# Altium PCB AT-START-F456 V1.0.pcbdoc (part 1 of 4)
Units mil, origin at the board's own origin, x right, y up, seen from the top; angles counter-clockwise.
Board outline 10942.5 x 3554 mil, 2 copper layers (Top Layer, Bottom Layer); 156 components, 201 nets, 759 pads, 796 vias.
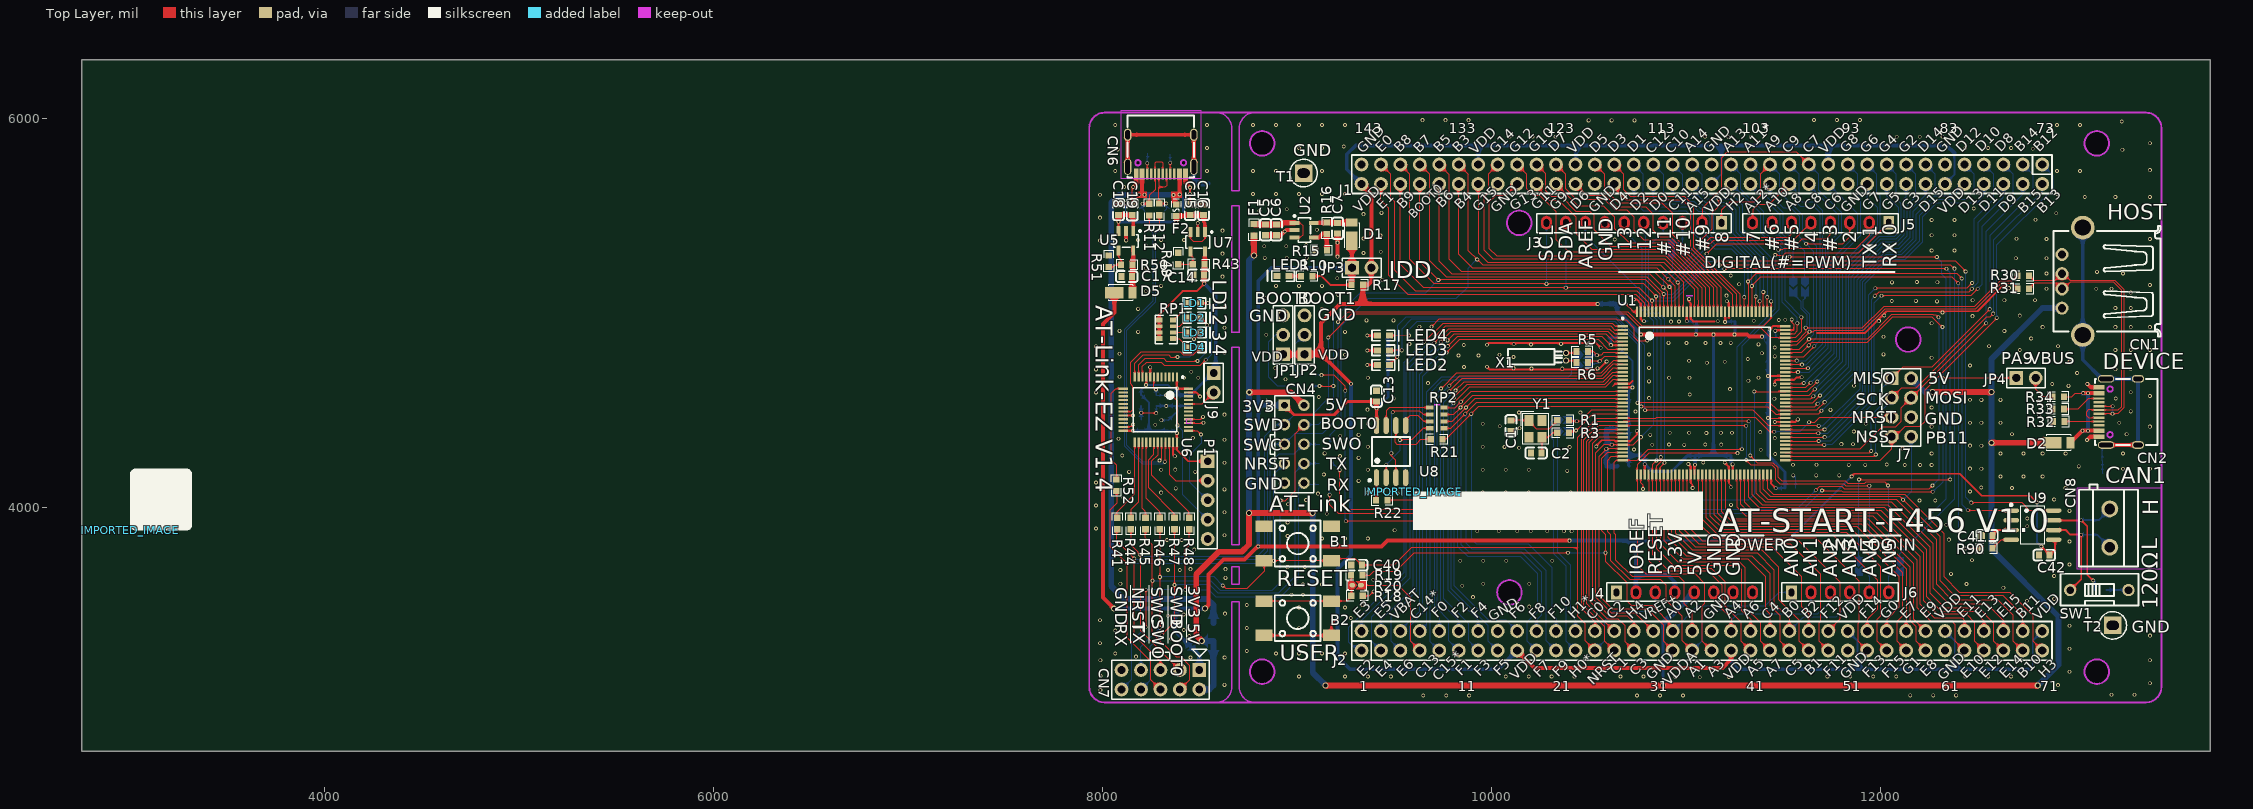
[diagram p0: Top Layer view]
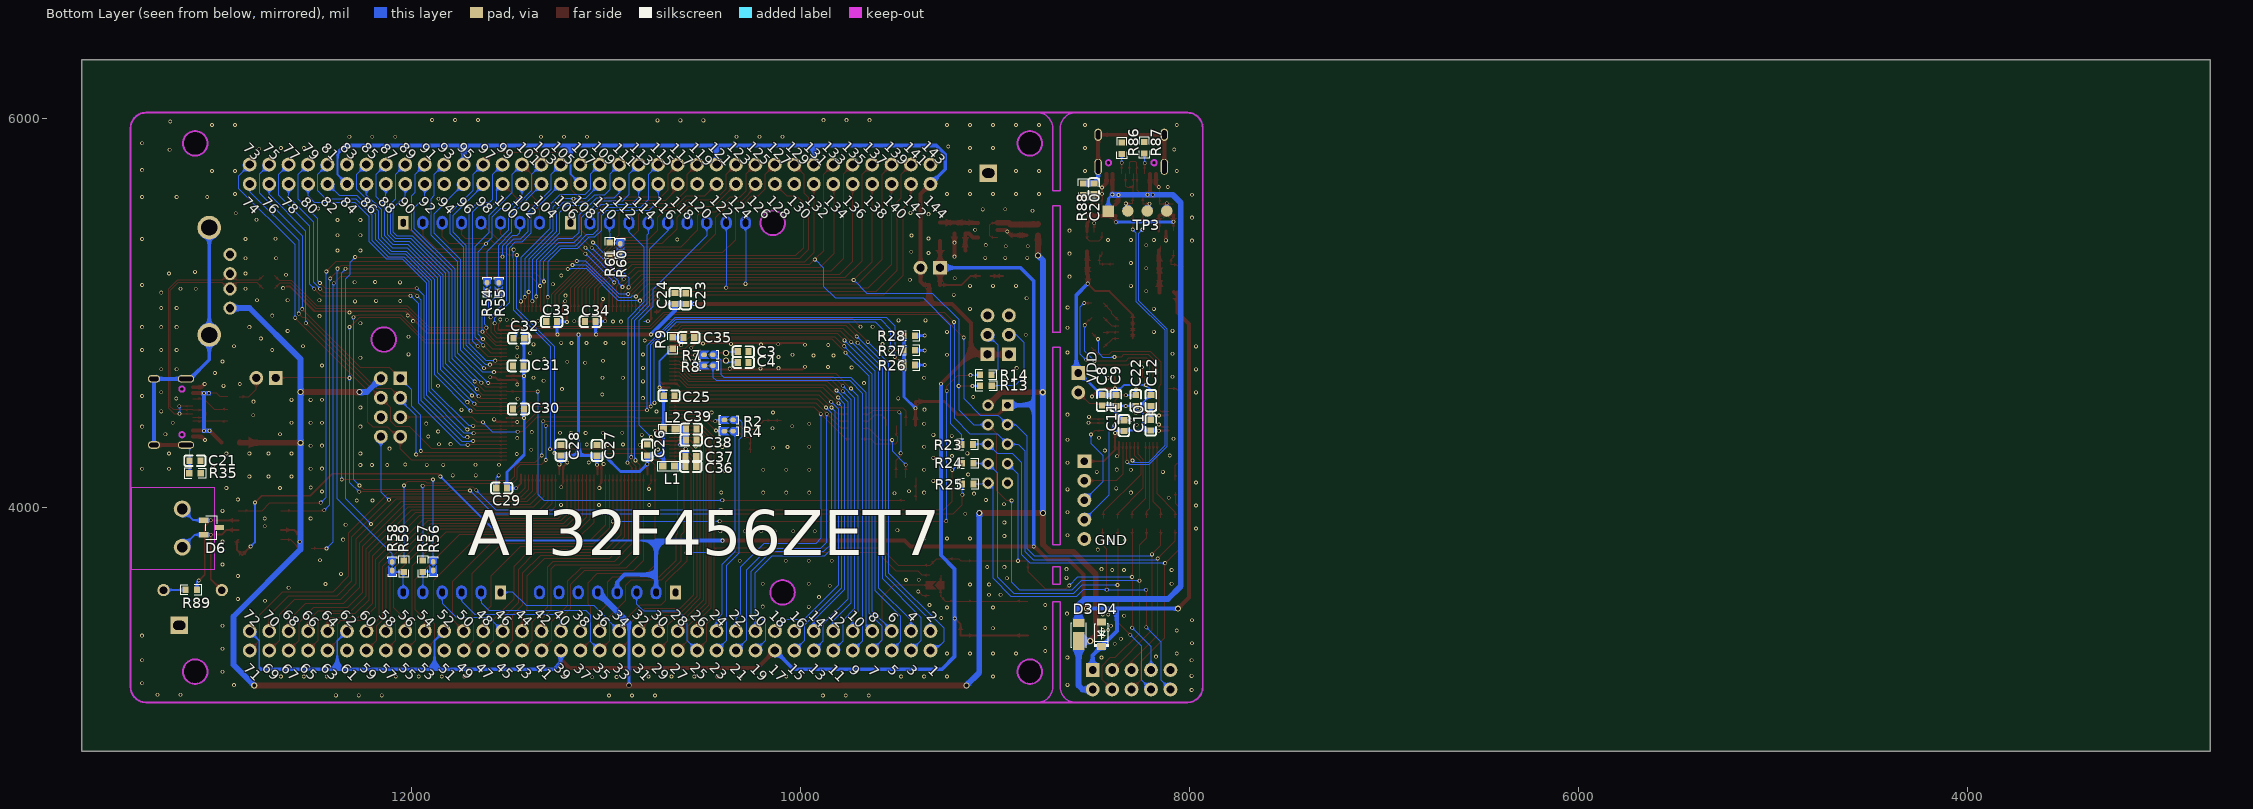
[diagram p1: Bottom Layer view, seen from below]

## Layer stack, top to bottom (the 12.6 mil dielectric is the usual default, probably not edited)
Top Layer: signal copper (thickness not stored)
Dielectric: dielectric 12.6, FR-4, Dk 4.8
Bottom Layer: signal copper (thickness not stored)

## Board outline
13692.5,2750 2750,2750 2750,6304 13692.5,6304
cut-out: 12202.8,4865.97 ccw(c12139.81,4865.43) 12076.82,4865.97 ccw(c12139.81,4866.51)
cut-out: 10202.8,5465.96 ccw(c10139.81,5465.42) 10076.82,5465.96 ccw(c10139.81,5466.5)
cut-out: 10152.8,3565.97 ccw(c10089.81,3565.43) 10026.82,3565.97 ccw(c10089.81,3566.51)
cut-out: 8881.38,5874.63 ccw(c8818.39,5874.09) 8755.4,5874.63 ccw(c8818.39,5875.17)
cut-out: 8881.38,3158.09 ccw(c8818.39,3157.55) 8755.4,3158.09 ccw(c8818.39,3158.63)
cut-out: 13172.72,3158.09 ccw(c13109.73,3157.55) 13046.74,3158.09 ccw(c13109.73,3158.63)
cut-out: 13172.72,5874.63 ccw(c13109.73,5874.09) 13046.74,5874.63 ccw(c13109.73,5875.17)

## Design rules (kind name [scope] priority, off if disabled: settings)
BoardOutlineClearance copperThickness1oz [All] p0: genericclearance=10 ignorepadtopadclearanceinfootprint=FALSE except(0: Arc-SplitContinuation Track-SplitContinuation SMDPad-SplitContinuation THPad-SplitContinuation Via-SplitContinuation Fill-SplitContinuation Poly-SplitContinuation Region-SplitContinuation Text-SplitContinuation; 6: SMDPad-CutoutEdge THPad-CutoutEdge Via-CutoutEdge Fill-CutoutEdge Region-CutoutEdge; 11.8: Track-OutlineEdge SMDPad-OutlineEdge THPad-OutlineEdge Via-OutlineEdge Fill-OutlineEdge Region-OutlineEdge Poly-OutlineEdge Text-OutlineEdge Track-CutoutEdge)
Clearance copperThickness1oz [(InNet('GND') OR InNet('PB11') OR InNet('PD4') OR InNet('PA1') OR InNet('PC1') OR InNet('PE15') OR InNet('PB10') OR InNet('PG6') OR InNet('PD10') OR InNet('PD9') OR InNet('PD8') OR InNet('PG15') OR InNet('PA2') OR InNet('PC0') OR InNet('PC2') OR InNet('NRST') OR InNet('PA15') OR InNet('PA13/SWDIO') OR InNet('PA14/SWCLK') OR InNet('VDD') OR InNet('PA3') OR InNet('PB2/BOOT1') OR InNet('3V3') OR InNet('PA0') OR InNet('PA5') OR InNet('PA6') OR InNet('PA7') OR InNet('PA9') OR InNet('PA10') OR InNet('PG14') OR InNet('PG13') OR InNet('PG11') OR InNet('PB5') OR InNet('PB6') OR InNet('PD2') OR InNet('PC12') OR InNet('PC11') OR InNet('PC10') OR InNet('VBAT') OR InNet('VDDA') OR InNet('VREF+') OR InNet('PD11') OR InNet('PD12') OR InNet('PD13') OR InNet('PD14') OR InNet('PD15') OR InNet('PG2') OR InNet('PG3') OR InNet('PG4') OR InNet('PG5') OR InNet('PG7') OR InNet('PG8') OR InNet('PC6') OR InNet('PC7') OR InNet('PC8') OR InNet('PC9') OR InNet('PA8') OR InNet('PH2') OR InNet('PH0/HEXT_IN') OR InNet('PH1/HEXT_OUT') OR InNet('PF10') OR InNet('PF9') OR InNet('PF8') OR InNet('PF7') OR InNet('PF6') OR InNet('PF5') OR InNet('PF4') OR InNet('PF3') OR InNet('PF2') OR InNet('PF1') OR InNet('PF0') OR InNet('PC13') OR InNet('PE6') OR InNet('PE5') OR InNet('PE4') OR InNet('PE3') OR InNet('PE2') OR InNet('PC15/LEXT_OUT') OR InNet('PC14/LEXT_IN') OR InNet('SWO') OR InNet('ATLK_RX') OR InNet('LD4') OR InNet('VCC') OR InNet('M-NRST') OR InNet('ATLK_TX') OR InNet('ATLINK_5V') OR InNet('PH3') OR InNet('PB3') OR InNet('QSPI1_IO2') OR InNet('QSPI1_IO1') OR InNet('PB4') OR InNet('PH1_E') OR InNet('PH0_E') OR InNet('PC15_E') OR InNet('PC14_E') OR InNet('PA11_E') OR InNet('PA12_E') OR InNet('PB0') OR InNet('PA4') OR InNet('PE10') OR InNet('PC4') OR InNet('VCC3.5V') OR InNet('PG0') OR InNet('PE7') OR InNet('PE8') OR InNet('PG1') OR InNet('LD3') OR InNet('LD2') OR InNet('LD1') OR InNet('VBUS1') OR InNet('PD3') OR InNet('PG9') OR InNet('PD6') OR InNet('M-SWDIO') OR InNet('M-ATLK_RX') OR InNet('M-ATLK_TX') OR InNet('PE1') OR InNet('PC3') OR InNet('PD7') OR InNet('PG10') OR InNet('PG12') OR InNet('M-SWCLK') OR InNet('PC5') OR InNet('PE12') OR InNet('PE11') OR InNet('PF15') OR InNet('PF14') OR InNet('PE13') OR InNet('PE14') OR InNet('PE9') OR InNet('PF12') OR InNet('PF13') OR InNet('PB1') OR InNet('PD5') OR InNet('PE0') OR InNet('QSPI1_SCK') OR InNet('PF11') OR InNet('QSPI1_IO0') OR InNet('QSPI1_IO3') OR InNet('$2N452') OR InNet('$2N453') OR InNet('$2N511') OR InNet('$2N512') OR InNet('$2N702') OR InNet('$2N701') OR InNet('$3N82') OR InNet('$3N81') OR InNet('$3N119') OR InNet('$3N184') OR InNet('$3N504') OR InNet('$3N505') OR InNet('$3N506') OR InNet('$4N269') OR InNet('$4N270') OR InNet('$4N339') OR InNet('$3N58') OR InNet('EGND1') OR InNet('OTGFS1_D-') OR InNet('OTGFS1_D+') OR InNet('PB12') OR InNet('PB13') OR InNet('PB14') OR InNet('PB15') OR InNet('PH4') OR InNet('QSPI1_CS') OR InNet('$3N17593') OR InNet('ATLK_SWCLK') OR InNet('$6N17598') OR InNet('ATLK_SWDIO') OR InNet('ATLK_BOOT0') OR InNet('ATLK_NRST') OR InNet('$6N17675') OR InNet('ATLK_SWO') OR InNet('PA11') OR InNet('PA12') OR InNet('$6N16959') OR InNet('EGND') OR InNet('$3N17443') OR InNet('$3N17484') OR InNet('CC2') OR InNet('USBP') OR InNet('USBM') OR InNet('CC1') OR InNet('M-BOOT0') OR InNet('$6N792') OR InNet('$6N793') OR InNet('$6N794') OR InNet('$6N795') OR InNet('M-USB_DP') OR InNet('M-USB_DM') OR InNet('5V') OR InNet('BOOT0') OR InNet('CAN_H') OR InNet('CAN_L') OR InNet('$3N25805') OR InNet('$3N25576') OR InNet('CAN1_STB') OR InNet('CAN1_RX') OR InNet('CAN1_TX') OR InNet('PB8') OR InNet('PB9') OR InNet('VBUS'))] p1: gap=7 ignorepadtopadclearanceinfootprint=FALSE except(6: Track-Track Track-SMDPad SMDPad-SMDPad Track-THPad SMDPad-THPad THPad-THPad Track-Via SMDPad-Via THPad-Via Via-Via Track-Fill SMDPad-Fill THPad-Fill Via-Fill Fill-Fill SMDPad-Region THPad-Region Via-Region Fill-Region Region-Region Track-Poly SMDPad-Poly THPad-Poly Via-Poly Fill-Poly Poly-Poly Track-Text SMDPad-Text THPad-Text Via-Text Fill-Text Region-Text Poly-Text Text-Text; 6.9: Track-Hole SMDPad-Hole THPad-Hole Via-Hole Fill-Hole Region-Hole Poly-Hole Text-Hole Sheet-Hole; 11.8: Track-Region Region-Poly Track-Sheet SMDPad-Sheet THPad-Sheet Via-Sheet Fill-Sheet Region-Sheet Poly-Sheet Text-Sheet)
DiffPairsRouting differentialPair [All] p1: maxuncoupledlength=10 minlimit=5.9843 maxlimit=5.9843 mostfreqgap=5.9843 toplayer_minwidth=5 toplayer_prefwidth=10 toplayer_maxwidth=100 bottomlayer_minwidth=5 bottomlayer_prefwidth=10 bottomlayer_maxwidth=100
PasteMaskExpansion pasteMaskExpansion [All] p1: expansion=0
PlaneConnect innerPlane [All] p1: planeconnectstyle=Relief reliefexpansion=20 reliefentries=4 reliefconductorwidth=10 reliefairgap=10
PolygonConnect copperRegion [All] p1: connectstyle=Relief reliefentries=4 reliefconductorwidth=10 polygonreliefangle="90 Angle" airgapwidth=10
RoutingVias viaSize [All] p1: viastyle="Through Hole" holewidth=11.811 minholewidth=11.811 maxholewidth=19.685 width=19.685 minwidth=19.685 maxwidth=31.496
SolderMaskExpansion solderMaskExpansion [All] p1: useseparateexpansions=TRUE expansion=2.0079 expansionbottom=2.0079
Width copperThickness1oz [All] p1: maxlimit=100 minlimit=6 preferedwidth=6

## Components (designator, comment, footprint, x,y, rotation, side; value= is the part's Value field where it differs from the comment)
B1 "贴片按键6*6*5 黑色" SW-SMD_4P-L6.0-W6.0-P4.50-LS9.0 9001.26,3816.97 r180 top
B2 "贴片按键6*6*5 红色" SW-SMD_4P-L6.0-W6.0-P4.50-LS9.0 9001.26,3432.97 r180 top
C1 "CL10C150JB8NNNC" C0603 10097.57,4422.61 r90 top
C2 "CL10C150JB8NNNC" C0603 10227.57,4282.61 r0 top
C3 "CL10C180JB8NNNC" C0603 10292.39,4803.64 r0 bottom
C4 "CL10C180JB8NNNC" C0603 10292.4,4748.08 r0 bottom
C5 "CL10A106KP8NNNC" C0603 8836.21,5429.61 r270 top
C6 "CC0603KRX7R9BB104" C0603 8891.21,5429.61 r270 top
C7 "CL10A106KP8NNNC" C0603 9206.21,5437.97 r270 top
C8 "CL10A475KO8NNNC" C0603 8446.37,4553.41 r90 bottom
C9 "CC0603KRX7R9BB104" C0603 8376.37,4552.61 r90 bottom
C10 "CC0603KRX7R9BB104" C0603 8196.77,4426.21 r270 bottom
C11 "CC0603KRX7R9BB104" C0603 8335.17,4423.41 r270 bottom
C12 "CC0603KRX7R9BB104" C0603 8196.37,4552.21 r90 bottom
C13 "CC0603KRX7R9BB104" C0603 9406.18,4574.85 r90 top
C14 "CL10A106KP8NNNC" C0603 8491.81,5197.16 r0 top
C15 "CL10A106KP8NNNC" C0603 8448.56,5534.05 r270 top
C16 "CC0603KRX7R9BB104" C0603 8517.56,5534.05 r270 top
C17 "CL10A106KP8NNNC" C0603 8122.56,5189.05 r0 top
C18 "CL10A106KP8NNNC" C0603 8080.37,5533.81 r270 top
C19 "CC0603KRX7R9BB104" C0603 8150.37,5533.01 r270 top
C20 "CC0603KRX7R9BB104" C0603 8489.57,5640.61 r90 bottom
C21 "CC0603KRX7R9BB104" C0603 13110.57,4242.61 r180 bottom
C22 "CC0603KRX7R9BB104" C0603 8273.97,4552.21 r90 bottom
C23 "CL10A475KO8NNNC" C0603 10587.57,5076.61 r90 bottom
C24 "CC0603KRX7R9BB104" C0603 10643.21,5076.97 r90 bottom
C25 "CC0603KRX7R9BB104" C0603 10673.21,4576.97 r180 bottom
C26 "CC0603KRX7R9BB104" C0603 10785.21,4297.97 r90 bottom
C27 "CC0603KRX7R9BB104" C0603 11043.21,4295.97 r90 bottom
C28 "CC0603KRX7R9BB104" C0603 11228.21,4296.97 r90 bottom
C29 "CC0603KRX7R9BB104" C0603 11534.21,4101.97 r0 bottom
C30 "CC0603KRX7R9BB104" C0603 11447.57,4508.61 r0 bottom
C31 "CC0603KRX7R9BB104" C0603 11448.57,4730.61 r0 bottom
C32 "CC0603KRX7R9BB104" C0603 11445.57,4872.61 r0 bottom
C33 "CC0603KRX7R9BB104" C0603 11277.21,4957.97 r0 bottom
C34 "CC0603KRX7R9BB104" C0603 11078.21,4958.97 r0 bottom
C35 "CC0603KRX7R9BB104" C0603 10571.21,4875.97 r180 bottom
C36 "CL10A105KB8NNNC" C0603 10561.21,4212.97 r180 bottom
C37 "CC0603KRX7R9BB104" C0603 10561.21,4264.97 r180 bottom
C38 "CC0603KRX7R9BB104" C0603 10559.57,4348.61 r180 bottom
C39 "CL10A105KB8NNNC" C0603 10559.21,4404.97 r180 bottom
C40 "CC0603KRX7R9BB104" C0603 9304.21,3705.97 r180 top
C41 "CC0603KRX7R9BB104" C0603 12545.57,3858.61 r0 top
C42 "CC0603KRX7R9BB104" C0603 12839.26,3757.22 r0 top
CN1 "JTJ-USB-AF-08" USB-A-TH__USB-AF-90 12984.07,5165.3 r90 top
CN2 "TYPEC-304-BCP16" USB-C-SMD_TYPEC-304-BCP16#1 13221.24,4493.82 r90 top locked
CN4 "CON10A_0" HDR2X5#1 8933.23,4527.98 r270 top
CN6 "TYPEC-304-BCP16" USB-C-SMD_TYPEC-304-BCP16#2 8297.21,5818.2 r180 top locked
CN7 "CON10" HDR2X5#2 8495.46,3166.58 r180 top
CN8 "KF301-5.0-2P" CONN-TH_P5.00_KF301-5.0-2P 13176.57,3896.61 r90 top
D1 "DFLS130L-7" POWERDI-123_L2.8-W1.8-LS3.7-RD 9280.21,5419.98 r90 top
D2 "DFLS130L-7" POWERDI-123_L2.8-W1.8-LS3.7-RD 12927.64,4335.82 r0 top
D3 "DFLS130L-7" POWERDI-123_L2.8-W1.8-LS3.7-RD 8567.57,3362.61 r90 bottom
D4 "SMF3.3A_C2759873" SOD-123FL_L2.8-W1.8-LS3.8-RD 8449.57,3350.61 r90 bottom
D5 "DFLS130L-7" POWERDI-123_L2.8-W1.8-LS3.7-RD 8105.61,5107.05 r0 top
D6 "PESD2CANFD24V-TR" SOT-23-3_L2.9-W1.3-P1.90-LS2.4-BR 13026.57,3899.61 r0 bottom
F1 "SMD0603B050TF" R0603 8776.26,5429.58 r90 top
F2 "BSMD0603-050-6V" F0603 8377.56,5531.05 r270 top
IMPORTED_IMAGE "IMPORTED_IMAGE" IMPORTED_IMAGE 3000,3885.66 r0 top
IMPORTED_IMAGE "IMPORTED_IMAGE" IMPORTED_IMAGE 9595.42,4083.65 r0 top
J1 "HDR 2X36" HDR_2.54_2X36 11079.18,5715.65 r180 top locked
J2 "HDR 2X36" HDR_2.54_2X36 11079.18,3317.07 r0 top locked
J3 "CON10" "FEMALE HEADER 1X10" 10729.8,5465.97 r0 top locked
J4 "CON8" "FEMALE HEADER 1X8" 10989.8,3565.97 r0 top locked
J5 "CON8" "FEMALE HEADER 1X8" 11689.8,5465.97 r180 top locked
J6 "CON6" "FEMALE HEADER 1X6" 11789.8,3565.97 r0 top locked
J7 "Header 4X2" HDR2X4 12054.8,4666.56 r270 top locked
J9 "1X2P_2.54M" HDR1X2 8569.46,4693.58 r270 top
JP1 "Jumper 1x3P" "HEADER 1X3" 8926.21,4789.97 r90 top
JP2 "Jumper 1x3P" "HEADER 1X3" 9036.21,4789.97 r90 top
JP3 "Jumper 1x2P" "HEADER 1X2" 9280.21,5234.97 r0 top
JP4 "Jumper 1x2P" "HEADER 1X2" 12695.57,4668.61 r0 top
L1 "0.5A,600Ω@100Mhz" 0603_L 10675.26,4214.98 r180 bottom
L2 "0.5A,600Ω@100Mhz" 0603_L 10671.57,4406.61 r180 bottom
LD1 "RED" LED0603 8439.47,5052.43 r0 top
LD2 "GREEN" LED0603 8440.43,4978.33 r0 top
LD3 "BLUE" LED0603 8440.47,4901.43 r0 top
LD4 "YELLOW" LED0603 8440.43,4825.43 r0 top
LED1 "RED" LED0603 8956.21,5192.97 r180 top
LED2 "RED" LED0603 9411.05,4735 r0 top
LED3 "YELLOW" LED0603 9411.06,4809.98 r0 top
LED4 "GREEN" LED0603 9411.06,4886.28 r0 top
P1 "Header 5" HDR1X5 8538.16,4240.18 r270 top
R1 "0603WAF0000T5E" R0603 10365.57,4450.61 r0 top
R2 "NC" SB-PAD 10367.57,4452.61 r0 bottom
R3 "0603WAF0000T5E" R0603 10365.57,4386.61 r0 top
R4 "NC" SB-PAD 10367.57,4394.61 r0 bottom
R5 "0603WAF0000T5E" R0603 10463.93,4804.45 r0 top
R6 "0603WAF0000T5E" R0603 10463.93,4747.72 r0 top
R7 "NC" SB-PAD 10471.84,4787.44 r0 bottom
R8 "NC" SB-PAD 10470.9,4731.54 r0 bottom
R9 "0603WAF0000T5E" R0603 10655.21,4847.97 r270 bottom
R10 "0603WAF1001T5E" R0603 9048.26,5191.98 r180 top
R11 "0603WAF0000T5E" R0603 8238.07,5534.03 r270 top
R12 "0603WAF0000T5E" R0603 8290.08,5534.82 r270 top
R13 "0603WAF1002T5E" R0603 9044.21,4627.97 r0 bottom
R14 "0603WAF1002T5E" R0603 9045.21,4683.97 r0 bottom
R15 "0603WAF1502T5E" R0603 9122.21,5323.97 r180 top
R16 "0603WAF5102T5E" R0603 9150.21,5437.97 r90 top
R17 "0603WAF0000T5E" R0603 9308.21,5146.97 r0 top
R18 "0603WAF1003T5E" R0603 9306.21,3547.97 r180 top
R19 "0603WAF0000T5E" R0603 9305.21,3653.97 r0 top
R20 "NC" SB-PAD 9305.21,3602.97 r0 top
R21 "0603WAF330JT5E" R0603 9715.18,4353.85 r180 top
R22 "0603WAF330JT5E" R0603 9433.51,4039.99 r180 top
R23 "0603WAF4700T5E" R0603 9140.26,4325.98 r0 bottom
R24 "0603WAF4700T5E" R0603 9138.26,4229.98 r0 bottom
R25 "0603WAF4700T5E" R0603 9137.66,4123.08 r0 bottom
R26 "0603WAF1001T5E" R0603 9437.86,4735 r180 bottom
R27 "0603WAF1001T5E" R0603 9437.86,4810 r180 bottom
R28 "0603WAF1001T5E" R0603 9437.86,4886.3 r180 bottom
R30 "0603WAF0000T5E" R0603 12730.98,5194.62 r0 top
R31 "0603WAF0000T5E" R0603 12730.98,5127.69 r0 top
R32 "0603WAF5101T5E" R0603 12913.57,4444.61 r0 top
R33 "0603WAF5101T5E" R0603 12911.57,4508.61 r0 top
R34 "0603WAF1002T5E" R0603 12911.57,4572.61 r0 top
R35 "RC0603FR-071ML" R0603 13110.57,4178.61 r0 bottom
R41 "0603WAF330JT5E" R0603 8073.66,3920.18 r270 top
R43 "0603WAF4702T5E" R0603 8491.56,5253.41 r180 top
R44 "0603WAF330JT5E" R0603 8143.66,3920.18 r270 top
R45 "0603WAF330JT5E" R0603 8218.66,3920.18 r270 top
R46 "0603WAF330JT5E" R0603 8292.66,3920.18 r270 top
R47 "0603WAF330JT5E" R0603 8367.66,3920.18 r270 top
R48 "0603WAF330JT5E" R0603 8443.66,3920.18 r270 top
R49 "0603WAF1502T5E" R0603 8387.57,5282.61 r90 top
R50 "0603WAF5102T5E" R0603 8122.56,5251.05 r180 top
R51 "0603WAF1502T5E" R0603 8029.57,5268.61 r90 top
R52 "0603WAF330JT5E" R0603 8068.66,4117.18 r270 top
R54 "NC" SB-PAD 11609.39,5135.54 r270 bottom
R55 "NC" SB-PAD 11549.03,5134.76 r270 bottom
R56 "NC" SB-PAD 11886.21,3699.97 r270 bottom
R57 "0603WAF0000T5E" R0603 11940.21,3699.97 r270 bottom
R58 "NC" SB-PAD 12096.95,3699.18 r270 bottom
R59 "0603WAF0000T5E" R0603 12037.06,3699.96 r270 bottom
R60 "NC" SB-PAD 10923.85,5335.18 r270 bottom
R61 "0603WAF0000T5E" R0603 10979.21,5334.97 r90 bottom
R86 "0603WAF5101T5E" R0603 8345.57,5848.61 r90 bottom
R87 "0603WAF5101T5E" R0603 8229.57,5852.61 r90 bottom
R88 "RC0603FR-071ML" R0603 8543.57,5638.61 r270 bottom
R89 "0603WAF1200T5E" R0603 13130.57,3578.61 r180 bottom
R90 "0603WAF3300T5E" R0603 12543.57,3792.61 r0 top
RP1 "4D03WGJ0102T5E" RES-ARRAY-SMD_0603-8P-L3.2-W1.6-BL 8324.77,4918.21 r270 top
RP2 "33R" 0603*4,8P4R 9753.18,4409.85 r90 top
SW1 "DSWB01LHGET" SW-TH_DSWB01LHGET 13122.57,3577.61 r90 top
T1 "TESTPOINT TP-5006" TESTHOOK 9031.47,5721.74 r0 top
T2 "TESTPOINT TP-5006" TESTHOOK 13191.57,3396.61 r0 top
TP3 "1X4P_2.54F" "HDR1X4 - TOP" 8414.58,5526.61 r0 bottom
U1 "AT32F457ZET7" LQFP144_20*20 11090.17,4589.99 r0 top locked
U2 "RT9080N-08GJ5" SOT-23-5 9049.21,5365.97 r0 top
U5 "RT9080N-08GJ5" SOT-23-5 8055.56,5359.05 r270 top
U6 "AT32F403ACCT7" "LQFP48 - 2" 8380.17,4672.63 r270 top locked
U7 "RT9080N-08GJ5" SOT-23-5 8424.34,5353.39 r270 top
U8 "EN25QH128A-104HIP" SOIC-8_208MIL 9481.16,4289.78 r0 top locked
U9 "MCP2562FD-E/SN" SOIC-8_L4.9-W3.9-P1.27-LS6.0-BL 12778.57,3911.61 r270 top
X1 "X206032768KGB2SC" OSC-TH_BD2.0-P0.70-D0.3 10380.73,4777.16 r0 top
Y1 "CJ13-080001210B20" CRYSTAL-SMD_4P-L3.2-W2.5-BL 10223.57,4406.61 r270 top

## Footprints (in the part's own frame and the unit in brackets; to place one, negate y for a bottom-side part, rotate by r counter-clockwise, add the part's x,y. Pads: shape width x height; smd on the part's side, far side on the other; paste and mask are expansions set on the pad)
0603*4,8P4R [mm]
  rect 0.55x0.95 smd: 1(0,0) 4(2.7,0) 5(2.7,1.85) 8(0,1.85)
  rect 0.5x0.95 smd: 2(0.9,0) 3(1.8,0) 6(1.8,1.85) 7(0.9,1.85)
  silkscreen extent -0.43,0.94 3.1,0.94
0603_L [mm]
  rect 0.93x0.9 smd: 1(-0.77,0) 2(0.77,0)
  silkscreen extent -1.4,-0.64 1.4,0.64
C0603 [mm]
  rect 0.8x0.9 smd: 1(-0.7,0) 2(0.7,0)
  silkscreen extent -1.41,-0.71 1.39,0.72
CONN-TH_P5.00_KF301-5.0-2P [mm]
  round 2.2 hole 1.4: 1(-2.5,0) 2(2.5,0)
  silkscreen extent -5,-3.7 5.71,4
CRYSTAL-SMD_4P-L3.2-W2.5-BL [mm]
  rect 1.4x1.2 smd: 1(-1.1,-0.85) 2(1.1,-0.85) 3(1.1,0.85) 4(-1.1,0.85)
  silkscreen extent -2.26,-1.91 2.03,1.68
F0603 [mil]
  rect 31.75x34.02 smd: 1(-29.66,0) 2(29.66,0)
  silkscreen extent -55,-25 55,25
"FEMALE HEADER 1X6" [mm]
  rect 1.4x1.8 hole 0.7 slot 1 at 90 deg: 1(-6.35,0)
  oval 0.6x0.42 hole 0.7 slot 1 at 90 deg: 2(-3.81,0) 3(-1.27,0) 4(1.27,0) 5(3.81,0) 6(6.35,0)
  Top Layer region: 7.05,-0.2 6.956,-0.55 6.7,-0.806 6.35,-0.9 6,-0.806 5.744,-0.55 5.65,-0.2 5.65,0.2 5.744,0.55 6,0.806 6.35,0.9 6.7,0.806 6.956,0.55 7.05,0.2
  Top Layer region: 4.51,-0.2 4.416,-0.55 4.16,-0.806 3.81,-0.9 3.46,-0.806 3.204,-0.55 3.11,-0.2 3.11,0.2 3.204,0.55 3.46,0.806 3.81,0.9 4.16,0.806 4.416,0.55 4.51,0.2
  Top Layer region: 1.97,-0.2 1.876,-0.55 1.62,-0.806 1.27,-0.9 0.92,-0.806 0.664,-0.55 0.57,-0.2 0.57,0.2 0.664,0.55 0.92,0.806 1.27,0.9 1.62,0.806 1.876,0.55 1.97,0.2
  Top Layer region: -0.57,-0.2 -0.664,-0.55 -0.92,-0.806 -1.27,-0.9 -1.62,-0.806 -1.876,-0.55 -1.97,-0.2 -1.97,0.2 -1.876,0.55 -1.62,0.806 -1.27,0.9 -0.92,0.806 -0.664,0.55 -0.57,0.2
  Top Layer region: -3.11,-0.2 -3.204,-0.55 -3.46,-0.806 -3.81,-0.9 -4.16,-0.806 -4.416,-0.55 -4.51,-0.2 -4.51,0.2 -4.416,0.55 -4.16,0.806 -3.81,0.9 -3.46,0.806 -3.204,0.55 -3.11,0.2
  Bottom Layer region: 7.05,-0.2 6.956,-0.55 6.7,-0.806 6.35,-0.9 6,-0.806 5.744,-0.55 5.65,-0.2 5.65,0.2 5.744,0.55 6,0.806 6.35,0.9 6.7,0.806 6.956,0.55 7.05,0.2
  Bottom Layer region: 4.51,-0.2 4.416,-0.55 4.16,-0.806 3.81,-0.9 3.46,-0.806 3.204,-0.55 3.11,-0.2 3.11,0.2 3.204,0.55 3.46,0.806 3.81,0.9 4.16,0.806 4.416,0.55 4.51,0.2
  Bottom Layer region: 1.97,-0.2 1.876,-0.55 1.62,-0.806 1.27,-0.9 0.92,-0.806 0.664,-0.55 0.57,-0.2 0.57,0.2 0.664,0.55 0.92,0.806 1.27,0.9 1.62,0.806 1.876,0.55 1.97,0.2
  Bottom Layer region: -0.57,-0.2 -0.664,-0.55 -0.92,-0.806 -1.27,-0.9 -1.62,-0.806 -1.876,-0.55 -1.97,-0.2 -1.97,0.2 -1.876,0.55 -1.62,0.806 -1.27,0.9 -0.92,0.806 -0.664,0.55 -0.57,0.2
  Bottom Layer region: -3.11,-0.2 -3.204,-0.55 -3.46,-0.806 -3.81,-0.9 -4.16,-0.806 -4.416,-0.55 -4.51,-0.2 -4.51,0.2 -4.416,0.55 -4.16,0.806 -3.81,0.9 -3.46,0.806 -3.204,0.55 -3.11,0.2
  Multi-Layer region: 7.05,-0.2 6.956,-0.55 6.7,-0.806 6.35,-0.9 6,-0.806 5.744,-0.55 5.65,-0.2 5.65,0.2 5.744,0.55 6,0.806 6.35,0.9 6.7,0.806 6.956,0.55 7.05,0.2
  Multi-Layer region: 4.51,-0.2 4.416,-0.55 4.16,-0.806 3.81,-0.9 3.46,-0.806 3.204,-0.55 3.11,-0.2 3.11,0.2 3.204,0.55 3.46,0.806 3.81,0.9 4.16,0.806 4.416,0.55 4.51,0.2
  Multi-Layer region: 1.97,-0.2 1.876,-0.55 1.62,-0.806 1.27,-0.9 0.92,-0.806 0.664,-0.55 0.57,-0.2 0.57,0.2 0.664,0.55 0.92,0.806 1.27,0.9 1.62,0.806 1.876,0.55 1.97,0.2
  Multi-Layer region: -0.57,-0.2 -0.664,-0.55 -0.92,-0.806 -1.27,-0.9 -1.62,-0.806 -1.876,-0.55 -1.97,-0.2 -1.97,0.2 -1.876,0.55 -1.62,0.806 -1.27,0.9 -0.92,0.806 -0.664,0.55 -0.57,0.2
  Multi-Layer region: -3.11,-0.2 -3.204,-0.55 -3.46,-0.806 -3.81,-0.9 -4.16,-0.806 -4.416,-0.55 -4.51,-0.2 -4.51,0.2 -4.416,0.55 -4.16,0.806 -3.81,0.9 -3.46,0.806 -3.204,0.55 -3.11,0.2
  silkscreen extent -7.62,-1.17 7.62,1.27
"FEMALE HEADER 1X8" [mm]
  rect 1.4x1.8 hole 0.7 slot 1 at 90 deg: 1(-8.89,0)
  oval 0.6x0.42 hole 0.7 slot 1 at 90 deg: 2(-6.35,0) 3(-3.81,0) 4(-1.27,0) 5(1.27,0) 6(3.81,0) 7(6.35,0) 8(8.89,0)
  Top Layer region: 9.59,-0.2 9.496,-0.55 9.24,-0.806 8.89,-0.9 8.54,-0.806 8.284,-0.55 8.19,-0.2 8.19,0.2 8.284,0.55 8.54,0.806 8.89,0.9 9.24,0.806 9.496,0.55 9.59,0.2
  Top Layer region: 7.05,-0.2 6.956,-0.55 6.7,-0.806 6.35,-0.9 6,-0.806 5.744,-0.55 5.65,-0.2 5.65,0.2 5.744,0.55 6,0.806 6.35,0.9 6.7,0.806 6.956,0.55 7.05,0.2
  Top Layer region: 4.51,-0.2 4.416,-0.55 4.16,-0.806 3.81,-0.9 3.46,-0.806 3.204,-0.55 3.11,-0.2 3.11,0.2 3.204,0.55 3.46,0.806 3.81,0.9 4.16,0.806 4.416,0.55 4.51,0.2
  Top Layer region: 1.97,-0.2 1.876,-0.55 1.62,-0.806 1.27,-0.9 0.92,-0.806 0.664,-0.55 0.57,-0.2 0.57,0.2 0.664,0.55 0.92,0.806 1.27,0.9 1.62,0.806 1.876,0.55 1.97,0.2
  Top Layer region: -0.57,-0.2 -0.664,-0.55 -0.92,-0.806 -1.27,-0.9 -1.62,-0.806 -1.876,-0.55 -1.97,-0.2 -1.97,0.2 -1.876,0.55 -1.62,0.806 -1.27,0.9 -0.92,0.806 -0.664,0.55 -0.57,0.2
  Top Layer region: -3.11,-0.2 -3.204,-0.55 -3.46,-0.806 -3.81,-0.9 -4.16,-0.806 -4.416,-0.55 -4.51,-0.2 -4.51,0.2 -4.416,0.55 -4.16,0.806 -3.81,0.9 -3.46,0.806 -3.204,0.55 -3.11,0.2
  Top Layer region: -5.65,-0.2 -5.744,-0.55 -6,-0.806 -6.35,-0.9 -6.7,-0.806 -6.956,-0.55 -7.05,-0.2 -7.05,0.2 -6.956,0.55 -6.7,0.806 -6.35,0.9 -6,0.806 -5.744,0.55 -5.65,0.2
  Bottom Layer region: 9.59,-0.2 9.496,-0.55 9.24,-0.806 8.89,-0.9 8.54,-0.806 8.284,-0.55 8.19,-0.2 8.19,0.2 8.284,0.55 8.54,0.806 8.89,0.9 9.24,0.806 9.496,0.55 9.59,0.2
  Bottom Layer region: 7.05,-0.2 6.956,-0.55 6.7,-0.806 6.35,-0.9 6,-0.806 5.744,-0.55 5.65,-0.2 5.65,0.2 5.744,0.55 6,0.806 6.35,0.9 6.7,0.806 6.956,0.55 7.05,0.2
  Bottom Layer region: 4.51,-0.2 4.416,-0.55 4.16,-0.806 3.81,-0.9 3.46,-0.806 3.204,-0.55 3.11,-0.2 3.11,0.2 3.204,0.55 3.46,0.806 3.81,0.9 4.16,0.806 4.416,0.55 4.51,0.2
  Bottom Layer region: 1.97,-0.2 1.876,-0.55 1.62,-0.806 1.27,-0.9 0.92,-0.806 0.664,-0.55 0.57,-0.2 0.57,0.2 0.664,0.55 0.92,0.806 1.27,0.9 1.62,0.806 1.876,0.55 1.97,0.2
  Bottom Layer region: -0.57,-0.2 -0.664,-0.55 -0.92,-0.806 -1.27,-0.9 -1.62,-0.806 -1.876,-0.55 -1.97,-0.2 -1.97,0.2 -1.876,0.55 -1.62,0.806 -1.27,0.9 -0.92,0.806 -0.664,0.55 -0.57,0.2
  Bottom Layer region: -3.11,-0.2 -3.204,-0.55 -3.46,-0.806 -3.81,-0.9 -4.16,-0.806 -4.416,-0.55 -4.51,-0.2 -4.51,0.2 -4.416,0.55 -4.16,0.806 -3.81,0.9 -3.46,0.806 -3.204,0.55 -3.11,0.2
  Bottom Layer region: -5.65,-0.2 -5.744,-0.55 -6,-0.806 -6.35,-0.9 -6.7,-0.806 -6.956,-0.55 -7.05,-0.2 -7.05,0.2 -6.956,0.55 -6.7,0.806 -6.35,0.9 -6,0.806 -5.744,0.55 -5.65,0.2
  Multi-Layer region: 9.59,-0.2 9.496,-0.55 9.24,-0.806 8.89,-0.9 8.54,-0.806 8.284,-0.55 8.19,-0.2 8.19,0.2 8.284,0.55 8.54,0.806 8.89,0.9 9.24,0.806 9.496,0.55 9.59,0.2
  Multi-Layer region: 7.05,-0.2 6.956,-0.55 6.7,-0.806 6.35,-0.9 6,-0.806 5.744,-0.55 5.65,-0.2 5.65,0.2 5.744,0.55 6,0.806 6.35,0.9 6.7,0.806 6.956,0.55 7.05,0.2
  Multi-Layer region: 4.51,-0.2 4.416,-0.55 4.16,-0.806 3.81,-0.9 3.46,-0.806 3.204,-0.55 3.11,-0.2 3.11,0.2 3.204,0.55 3.46,0.806 3.81,0.9 4.16,0.806 4.416,0.55 4.51,0.2
  Multi-Layer region: 1.97,-0.2 1.876,-0.55 1.62,-0.806 1.27,-0.9 0.92,-0.806 0.664,-0.55 0.57,-0.2 0.57,0.2 0.664,0.55 0.92,0.806 1.27,0.9 1.62,0.806 1.876,0.55 1.97,0.2
  Multi-Layer region: -0.57,-0.2 -0.664,-0.55 -0.92,-0.806 -1.27,-0.9 -1.62,-0.806 -1.876,-0.55 -1.97,-0.2 -1.97,0.2 -1.876,0.55 -1.62,0.806 -1.27,0.9 -0.92,0.806 -0.664,0.55 -0.57,0.2
  Multi-Layer region: -3.11,-0.2 -3.204,-0.55 -3.46,-0.806 -3.81,-0.9 -4.16,-0.806 -4.416,-0.55 -4.51,-0.2 -4.51,0.2 -4.416,0.55 -4.16,0.806 -3.81,0.9 -3.46,0.806 -3.204,0.55 -3.11,0.2
  Multi-Layer region: -5.65,-0.2 -5.744,-0.55 -6,-0.806 -6.35,-0.9 -6.7,-0.806 -6.956,-0.55 -7.05,-0.2 -7.05,0.2 -6.956,0.55 -6.7,0.806 -6.35,0.9 -6,0.806 -5.744,0.55 -5.65,0.2
  silkscreen extent -10.16,-1.17 10.16,1.27
"FEMALE HEADER 1X10" [mm]
  rect 1.4x1.8 hole 0.7 slot 1 at 90 deg: 1(11.43,0)
  oval 0.6x0.42 hole 0.7 slot 1 at 90 deg: 2(8.89,0) 3(6.35,0) 4(3.81,0) 5(1.27,0) 6(-1.27,0) 7(-3.81,0) 8(-6.35,0) 9(-8.89,0) 10(-11.43,0)
  Top Layer region: -12.13,0.2 -12.036,0.55 -11.78,0.806 -11.43,0.9 -11.08,0.806 -10.824,0.55 -10.73,0.2 -10.73,-0.2 -10.824,-0.55 -11.08,-0.806 -11.43,-0.9 -11.78,-0.806 -12.036,-0.55 -12.13,-0.2
  Top Layer region: -9.59,0.2 -9.496,0.55 -9.24,0.806 -8.89,0.9 -8.54,0.806 -8.284,0.55 -8.19,0.2 -8.19,-0.2 -8.284,-0.55 -8.54,-0.806 -8.89,-0.9 -9.24,-0.806 -9.496,-0.55 -9.59,-0.2
  Top Layer region: -7.05,0.2 -6.956,0.55 -6.7,0.806 -6.35,0.9 -6,0.806 -5.744,0.55 -5.65,0.2 -5.65,-0.2 -5.744,-0.55 -6,-0.806 -6.35,-0.9 -6.7,-0.806 -6.956,-0.55 -7.05,-0.2
  Top Layer region: -4.51,0.2 -4.416,0.55 -4.16,0.806 -3.81,0.9 -3.46,0.806 -3.204,0.55 -3.11,0.2 -3.11,-0.2 -3.204,-0.55 -3.46,-0.806 -3.81,-0.9 -4.16,-0.806 -4.416,-0.55 -4.51,-0.2
  Top Layer region: -1.97,0.2 -1.876,0.55 -1.62,0.806 -1.27,0.9 -0.92,0.806 -0.664,0.55 -0.57,0.2 -0.57,-0.2 -0.664,-0.55 -0.92,-0.806 -1.27,-0.9 -1.62,-0.806 -1.876,-0.55 -1.97,-0.2
  Top Layer region: 0.57,0.2 0.664,0.55 0.92,0.806 1.27,0.9 1.62,0.806 1.876,0.55 1.97,0.2 1.97,-0.2 1.876,-0.55 1.62,-0.806 1.27,-0.9 0.92,-0.806 0.664,-0.55 0.57,-0.2
  Top Layer region: 3.11,0.2 3.204,0.55 3.46,0.806 3.81,0.9 4.16,0.806 4.416,0.55 4.51,0.2 4.51,-0.2 4.416,-0.55 4.16,-0.806 3.81,-0.9 3.46,-0.806 3.204,-0.55 3.11,-0.2
  Top Layer region: 5.65,0.2 5.744,0.55 6,0.806 6.35,0.9 6.7,0.806 6.956,0.55 7.05,0.2 7.05,-0.2 6.956,-0.55 6.7,-0.806 6.35,-0.9 6,-0.806 5.744,-0.55 5.65,-0.2
  Top Layer region: 8.19,0.2 8.284,0.55 8.54,0.806 8.89,0.9 9.24,0.806 9.496,0.55 9.59,0.2 9.59,-0.2 9.496,-0.55 9.24,-0.806 8.89,-0.9 8.54,-0.806 8.284,-0.55 8.19,-0.2
  Bottom Layer region: -12.13,0.2 -12.036,0.55 -11.78,0.806 -11.43,0.9 -11.08,0.806 -10.824,0.55 -10.73,0.2 -10.73,-0.2 -10.824,-0.55 -11.08,-0.806 -11.43,-0.9 -11.78,-0.806 -12.036,-0.55 -12.13,-0.2
  Bottom Layer region: -9.59,0.2 -9.496,0.55 -9.24,0.806 -8.89,0.9 -8.54,0.806 -8.284,0.55 -8.19,0.2 -8.19,-0.2 -8.284,-0.55 -8.54,-0.806 -8.89,-0.9 -9.24,-0.806 -9.496,-0.55 -9.59,-0.2
  Bottom Layer region: -7.05,0.2 -6.956,0.55 -6.7,0.806 -6.35,0.9 -6,0.806 -5.744,0.55 -5.65,0.2 -5.65,-0.2 -5.744,-0.55 -6,-0.806 -6.35,-0.9 -6.7,-0.806 -6.956,-0.55 -7.05,-0.2
  Bottom Layer region: -4.51,0.2 -4.416,0.55 -4.16,0.806 -3.81,0.9 -3.46,0.806 -3.204,0.55 -3.11,0.2 -3.11,-0.2 -3.204,-0.55 -3.46,-0.806 -3.81,-0.9 -4.16,-0.806 -4.416,-0.55 -4.51,-0.2
  Bottom Layer region: -1.97,0.2 -1.876,0.55 -1.62,0.806 -1.27,0.9 -0.92,0.806 -0.664,0.55 -0.57,0.2 -0.57,-0.2 -0.664,-0.55 -0.92,-0.806 -1.27,-0.9 -1.62,-0.806 -1.876,-0.55 -1.97,-0.2
  Bottom Layer region: 0.57,0.2 0.664,0.55 0.92,0.806 1.27,0.9 1.62,0.806 1.876,0.55 1.97,0.2 1.97,-0.2 1.876,-0.55 1.62,-0.806 1.27,-0.9 0.92,-0.806 0.664,-0.55 0.57,-0.2
  Bottom Layer region: 3.11,0.2 3.204,0.55 3.46,0.806 3.81,0.9 4.16,0.806 4.416,0.55 4.51,0.2 4.51,-0.2 4.416,-0.55 4.16,-0.806 3.81,-0.9 3.46,-0.806 3.204,-0.55 3.11,-0.2
  Bottom Layer region: 5.65,0.2 5.744,0.55 6,0.806 6.35,0.9 6.7,0.806 6.956,0.55 7.05,0.2 7.05,-0.2 6.956,-0.55 6.7,-0.806 6.35,-0.9 6,-0.806 5.744,-0.55 5.65,-0.2
  Bottom Layer region: 8.19,0.2 8.284,0.55 8.54,0.806 8.89,0.9 9.24,0.806 9.496,0.55 9.59,0.2 9.59,-0.2 9.496,-0.55 9.24,-0.806 8.89,-0.9 8.54,-0.806 8.284,-0.55 8.19,-0.2
  Multi-Layer region: -12.13,0.2 -12.036,0.55 -11.78,0.806 -11.43,0.9 -11.08,0.806 -10.824,0.55 -10.73,0.2 -10.73,-0.2 -10.824,-0.55 -11.08,-0.806 -11.43,-0.9 -11.78,-0.806 -12.036,-0.55 -12.13,-0.2
  Multi-Layer region: -9.59,0.2 -9.496,0.55 -9.24,0.806 -8.89,0.9 -8.54,0.806 -8.284,0.55 -8.19,0.2 -8.19,-0.2 -8.284,-0.55 -8.54,-0.806 -8.89,-0.9 -9.24,-0.806 -9.496,-0.55 -9.59,-0.2
  Multi-Layer region: -7.05,0.2 -6.956,0.55 -6.7,0.806 -6.35,0.9 -6,0.806 -5.744,0.55 -5.65,0.2 -5.65,-0.2 -5.744,-0.55 -6,-0.806 -6.35,-0.9 -6.7,-0.806 -6.956,-0.55 -7.05,-0.2
  Multi-Layer region: -4.51,0.2 -4.416,0.55 -4.16,0.806 -3.81,0.9 -3.46,0.806 -3.204,0.55 -3.11,0.2 -3.11,-0.2 -3.204,-0.55 -3.46,-0.806 -3.81,-0.9 -4.16,-0.806 -4.416,-0.55 -4.51,-0.2
  Multi-Layer region: -1.97,0.2 -1.876,0.55 -1.62,0.806 -1.27,0.9 -0.92,0.806 -0.664,0.55 -0.57,0.2 -0.57,-0.2 -0.664,-0.55 -0.92,-0.806 -1.27,-0.9 -1.62,-0.806 -1.876,-0.55 -1.97,-0.2
  Multi-Layer region: 0.57,0.2 0.664,0.55 0.92,0.806 1.27,0.9 1.62,0.806 1.876,0.55 1.97,0.2 1.97,-0.2 1.876,-0.55 1.62,-0.806 1.27,-0.9 0.92,-0.806 0.664,-0.55 0.57,-0.2
  Multi-Layer region: 3.11,0.2 3.204,0.55 3.46,0.806 3.81,0.9 4.16,0.806 4.416,0.55 4.51,0.2 4.51,-0.2 4.416,-0.55 4.16,-0.806 3.81,-0.9 3.46,-0.806 3.204,-0.55 3.11,-0.2
  Multi-Layer region: 5.65,0.2 5.744,0.55 6,0.806 6.35,0.9 6.7,0.806 6.956,0.55 7.05,0.2 7.05,-0.2 6.956,-0.55 6.7,-0.806 6.35,-0.9 6,-0.806 5.744,-0.55 5.65,-0.2
  Multi-Layer region: 8.19,0.2 8.284,0.55 8.54,0.806 8.89,0.9 9.24,0.806 9.496,0.55 9.59,0.2 9.59,-0.2 9.496,-0.55 9.24,-0.806 8.89,-0.9 8.54,-0.806 8.284,-0.55 8.19,-0.2
  silkscreen extent -12.67,-1.27 12.7,1.17
HDR1X2 [mm]
  rect 1.8x1.8 hole 1: 1(0,0)
  round 1.8 hole 1: 2(2.54,0)
  silkscreen extent -1.27,-1.27 3.81,1.27
"HDR1X4 - TOP" [mm]
  rect 1.5x1.5 smd: 1(0,0)
  round 1.5 smd: 2(-2.54,0) 3(-5.08,0) 4(-7.62,0)
HDR1X5 [mm]
  rect 1.8x1.8 hole 1: 1(0,0)
  round 1.8 hole 1: 2(2.54,0) 3(5.08,0) 4(7.62,0) 5(10.16,0)
  silkscreen extent -1.27,-1.27 11.43,1.27
HDR2X4 [mm]
  rect 1.8x1.8 hole 1 slot 1.005 at 0 deg: 1(0,0)
  round 1.8 hole 1 slot 1.005 at 0 deg: 2(0,2.54) 3(2.54,0) 4(2.54,2.54) 5(5.08,0) 6(5.08,2.54) 7(7.62,0) 8(7.62,2.54)
  silkscreen extent -1.27,-1.27 8.89,3.81
HDR2X5#1 [mm]
  rect 1.5x1.5 hole 0.9: 1(0,0)
  round 1.5 hole 0.9: 2(0,2.54) 3(2.54,0) 4(2.54,2.54) 5(5.08,0) 6(5.08,2.54) 7(7.62,0) 8(7.62,2.54) 9(10.16,0) 10(10.16,2.54)
  silkscreen extent -1.27,-1.27 11.43,3.81
HDR2X5#2 [mm]
  rect 1.8x1.8 hole 1: 1(0,0)
  round 1.8 hole 1: 2(0,2.54) 3(2.54,0) 4(2.54,2.54) 5(5.08,0) 6(5.08,2.54) 7(7.62,0) 8(7.62,2.54) 9(10.16,0) 10(10.16,2.54)
  silkscreen extent -1.27,-1.27 11.43,3.81
HDR_2.54_2X36 [mm]
  round 1.8 hole 1.1: 1(-44.45,-1.27) 2(-44.45,1.27) 3(-41.91,-1.27) 4(-41.91,1.27) 5(-39.37,-1.27) 6(-39.37,1.27) 7(-36.83,-1.27) 8(-36.83,1.27) 9(-34.29,-1.27) 10(-34.29,1.27) 11(-31.75,-1.27) 12(-31.75,1.27) 13(-29.21,-1.27) 14(-29.21,1.27) 15(-26.67,-1.27) 16(-26.67,1.27) 17(-24.13,-1.27) 18(-24.13,1.27) 19(-21.59,-1.27) 20(-21.59,1.27) 21(-19.05,-1.27) 22(-19.05,1.27) 23(-16.51,-1.27) 24(-16.51,1.27) 25(-13.97,-1.27) 26(-13.97,1.27) 27(-11.43,-1.27) 28(-11.43,1.27) 29(-8.89,-1.27) 30(-8.89,1.27) 31(-6.35,-1.27) 32(-6.35,1.27) 33(-3.81,-1.27) 34(-3.81,1.27) 35(-1.27,-1.27) 36(-1.27,1.27) 37(1.27,-1.27) 38(1.27,1.27) 39(3.81,-1.27) 40(3.81,1.27) 41(6.35,-1.27) 42(6.35,1.27) 43(8.89,-1.27) 44(8.89,1.27) 45(11.43,-1.27) 46(11.43,1.27) 47(13.97,-1.27) 48(13.97,1.27) 49(16.51,-1.27) 50(16.51,1.27) 51(19.05,-1.27) 52(19.05,1.27) 53(21.59,-1.27) 54(21.59,1.27) 55(24.13,-1.27) 56(24.13,1.27) 57(26.67,-1.27) 58(26.67,1.27) 59(29.21,-1.27) 60(29.21,1.27) 61(31.75,-1.27) 62(31.75,1.27) 63(34.29,-1.27) 64(34.29,1.27) 65(36.83,-1.27) 66(36.83,1.27) 67(39.37,-1.27) 68(39.37,1.27) 69(41.91,-1.27) 70(41.91,1.27) 71(44.45,-1.27) 72(44.45,1.27)
  silkscreen extent -45.72,-2.54 45.72,2.54
"HEADER 1X2" [mm]
  rect 1.8x1.8 hole 1 slot 1.005 at 0 deg: 1(0,0)
  round 1.8 hole 1 slot 1.005 at 0 deg: 2(2.54,0)
  silkscreen extent -1.27,-1.27 3.81,1.27
"HEADER 1X3" [mm]
  rect 1.8x1.8 hole 1 slot 1.005 at 0 deg: 1(0,0)
  round 1.8 hole 1 slot 1.005 at 0 deg copper offset 0,0: 2(2.54,0) 3(5.08,0)
  silkscreen extent -1.27,-1.27 6.35,1.27
IMPORTED_IMAGE [mil]
  silkscreen extent 0,0 315,315
LED0603 [mil]
  rect 36x32 smd: 1(-0.04,0.2) 2(60.96,0.2)
  silkscreen extent -28,-28 110,27
"LQFP48 - 2" [mm]
  rect 1.2x0.3 smd: 1(0,0) 2(0,-0.5) 3(0,-1) 4(0,-1.5) 5(0,-2) 6(0,-2.5) 7(0,-3) 8(0,-3.5) 9(0,-4) 10(0,-4.5) 11(0,-5) 12(0,-5.5) 25(8.5,-5.5) 26(8.5,-5) 27(8.5,-4.5) 28(8.5,-4) 29(8.5,-3.5) 30(8.5,-3) 31(8.5,-2.5) 32(8.5,-2) 33(8.5,-1.5) 34(8.5,-1) 35(8.5,-0.5) 36(8.5,0)
  rect 0.3x1.2 smd: 13(1.5,-7) 14(2,-7) 15(2.5,-7) 16(3,-7) 17(3.5,-7) 18(4,-7) 19(4.5,-7) 20(5,-7) 21(5.5,-7) 22(6,-7) 23(6.5,-7) 24(7,-7) 37(7,1.5) 38(6.5,1.5) 39(6,1.5) 40(5.5,1.5) 41(5,1.5) 42(4.5,1.5) 43(4,1.5) 44(3.5,1.5) 45(3,1.5) 46(2.5,1.5) 47(2,1.5) 48(1.5,1.5)
  silkscreen extent -0.12,-5.71 7.11,0.89
LQFP144_20*20 [mm]
  rect 1.35x0.3 smd: 1(-10.625,8.75) 2(-10.625,8.25) 3(-10.625,7.75) 4(-10.625,7.25) 5(-10.625,6.75) 6(-10.625,6.25) 7(-10.625,5.75) 8(-10.625,5.25) 9(-10.625,4.75) 10(-10.625,4.25) 11(-10.625,3.75) 12(-10.625,3.25) 13(-10.625,2.75) 14(-10.625,2.25) 15(-10.625,1.75) 16(-10.625,1.25) 17(-10.625,0.75) 18(-10.625,0.25) 19(-10.625,-0.25) 20(-10.625,-0.75) 21(-10.625,-1.25) 22(-10.625,-1.75) 23(-10.625,-2.25) 24(-10.625,-2.75) 25(-10.625,-3.25) 26(-10.625,-3.75) 27(-10.625,-4.25) 28(-10.625,-4.75) 29(-10.625,-5.25) 30(-10.625,-5.75) 31(-10.625,-6.25) 32(-10.625,-6.75) 33(-10.625,-7.25) 34(-10.625,-7.75) 35(-10.625,-8.25) 36(-10.625,-8.75) 73(10.625,-8.75) 74(10.625,-8.25) 75(10.625,-7.75) 76(10.625,-7.25) 77(10.625,-6.75) 78(10.625,-6.25) 79(10.625,-5.75) 80(10.625,-5.25) 81(10.625,-4.75) 82(10.625,-4.25) 83(10.625,-3.75) 84(10.625,-3.25) 85(10.625,-2.75) 86(10.625,-2.25) 87(10.625,-1.75) 88(10.625,-1.25) 89(10.625,-0.75) 90(10.625,-0.25) 91(10.625,0.25) 92(10.625,0.75) 93(10.625,1.25) 94(10.625,1.75) 95(10.625,2.25) 96(10.625,2.75) 97(10.625,3.25) 98(10.625,3.75) 99(10.625,4.25) 100(10.625,4.75) 101(10.625,5.25) 102(10.625,5.75) 103(10.625,6.25) 104(10.625,6.75) 105(10.625,7.25) 106(10.625,7.75) 107(10.625,8.25) 108(10.625,8.75)
  rect 0.3x1.35 smd: 37(-8.75,-10.625) 38(-8.25,-10.625) 39(-7.75,-10.625) 40(-7.25,-10.625) 41(-6.75,-10.625) 42(-6.25,-10.625) 43(-5.75,-10.625) 44(-5.25,-10.625) 45(-4.75,-10.625) 46(-4.25,-10.625) 47(-3.75,-10.625) 48(-3.25,-10.625) 49(-2.75,-10.625) 50(-2.25,-10.625) 51(-1.75,-10.625) 52(-1.25,-10.625) 53(-0.75,-10.625) 54(-0.25,-10.625) 55(0.25,-10.625) 56(0.75,-10.625) 57(1.25,-10.625) 58(1.75,-10.625) 59(2.25,-10.625) 60(2.75,-10.625) 61(3.25,-10.625) 62(3.75,-10.625) 63(4.25,-10.625) 64(4.75,-10.625) 65(5.25,-10.625) 66(5.75,-10.625) 67(6.25,-10.625) 68(6.75,-10.625) 69(7.25,-10.625) 70(7.75,-10.625) 71(8.25,-10.625) 72(8.75,-10.625) 109(8.75,10.625) 110(8.25,10.625) 111(7.75,10.625) 112(7.25,10.625) 113(6.75,10.625) 114(6.25,10.625) 115(5.75,10.625) 116(5.25,10.625) 117(4.75,10.625) 118(4.25,10.625) 119(3.75,10.625) 120(3.25,10.625) 121(2.75,10.625) 122(2.25,10.625) 123(1.75,10.625) 124(1.25,10.625) 125(0.75,10.625) 126(0.25,10.625) 127(-0.25,10.625) 128(-0.75,10.625) 129(-1.25,10.625) 130(-1.75,10.625) 131(-2.25,10.625) 132(-2.75,10.625) 133(-3.25,10.625) 134(-3.75,10.625) 135(-4.25,10.625) 136(-4.75,10.625) 137(-5.25,10.625) 138(-5.75,10.625) 139(-6.25,10.625) 140(-6.75,10.625) 141(-7.25,10.625) 142(-7.75,10.625) 143(-8.25,10.625) 144(-8.75,10.625)
  silkscreen extent -10.75,-8.78 8.68,9.89
OSC-TH_BD2.0-P0.70-D0.3 [mm]
  round 0.8 hole 0.5: 1(0,0.5) 2(0,-0.5)
  silkscreen extent -7.6,-1 -0.54,1
POWERDI-123_L2.8-W1.8-LS3.7-RD [mm]
  rect 2.4x1.5 smd: 1(-1.187,0)
  rect 1.05x1.5 smd: 2(1.187,0)
  silkscreen extent -2,-1 1.2,1
R0603 [mil]
  rect 31.75x34.02 smd: 1(-29.66,0) 2(29.66,0)
  silkscreen extent -55,-26 55,26
RES-ARRAY-SMD_0603-8P-L3.2-W1.6-BL [mm]
  rect 0.65x0.8 smd: 1(-1.2,-0.9) 4(1.2,-0.9) 5(1.2,0.9) 8(-1.2,0.9)
  rect 0.5x0.8 smd: 2(-0.4,-0.9) 3(0.4,-0.9) 6(0.4,0.9) 7(-0.4,0.9)
  silkscreen extent -1.87,-1.45 1.87,1.47
SB-PAD [mm]
  oval 0.735x0.6 smd: 1(-0.587,0)
  oval 0.791x0.6 smd: 2(0.541,0)
  Top Layer region: -1.2,-0.5 -1.2,0.5 -0.418,0.5 0.025,0 -0.433,-0.5
  Top Layer region: -0.119,0.5 0.381,0 -0.119,-0.5 1.2,-0.5 1.2,0.5
  silkscreen extent -1.28,-0.58 1.28,0.58
SOD-123FL_L2.8-W1.8-LS3.8-RD [mm]
  rect 0.93x1.2 smd: 1(-1.6,0) 2(1.6,0)
  silkscreen extent -1.6,-0.95 1.38,0.95
SOIC-8_208MIL [mm]
  oval 0.7x2.2 smd: 1(-1.905,-3.4) 2(-0.635,-3.4) 3(0.635,-3.4) 4(1.905,-3.4) 5(1.905,3.4) 6(0.635,3.4) 7(-0.635,3.4) 8(-1.905,3.4)
  silkscreen extent -2.95,-3.9 2.5,1.9
SOIC-8_L4.9-W3.9-P1.27-LS6.0-BL [mm]
  oval 0.588x2.045 smd: 1(-1.905,-2.772) 2(-0.635,-2.772) 3(0.635,-2.772) 4(1.905,-2.772) 5(1.905,2.772) 6(0.635,2.772) 7(-0.635,2.772) 8(-1.905,2.772)
  silkscreen extent -2.8,-2.92 2.53,1.52
SOT-23-3_L2.9-W1.3-P1.90-LS2.4-BR [mm]
  rect 1.25x0.7 smd: 1(1,-0.95) 2(1,0.95) 3(-1,0)
  silkscreen extent -0.73,-1.53 0.73,1.53
SOT-23-5 [mil]
  rect 50x20 smd: 1(-65,100) 2(-65,63) 3(-65,25) 4(35,25) 5(35,100)
  silkscreen extent -65,1 18,135
SW-SMD_4P-L6.0-W6.0-P4.50-LS9.0 [mm]
  rect 2.2x1.5 smd: 1(-4.4,2.25) 2(-4.4,-2.25) 3(4.4,2.25) 4(4.4,-2.25)
  silkscreen extent -3,-3 3,3
SW-TH_DSWB01LHGET [mm]
  round 1.6 hole 1: 1(0,3.81) 2(0,-3.81)
  silkscreen extent -2.02,-5.11 2.13,5.05
TESTHOOK [mm]
  rect 2.3x2.3 hole 1.2 slot 1.6 at 0 deg: 1(0,0)
  silkscreen extent -1.8,-1.8 1.8,1.8
USB-A-TH__USB-AF-90 [mm]
  round 1.7 hole 1.1 copper offset 0,0: 1(-3.5,1.355) 2(-1,1.355) 3(1,1.355) 4(3.5,1.355)
  round 3.1 hole 2.1: SH1(7,-1.355) SH2(-7,-1.355)
  silkscreen extent -7.22,-11.51 7.22,2.49
USB-C-SMD_TYPEC-304-BCP16#1 [mil]
  oval 39.4x82.7 hole 23.6 slot 70.9 at 90 deg: 13(-170.1,64.3) 14(170.1,64.3)
  oval 39.4x63 hole 23.6 slot 47.2 at 90 deg: 15(-170.1,-100.3) 16(170.1,-100.3)
  rect 23.6x57.1 smd: A1B12(-127,100.3) A4B9(-96.5,100.3) B1A12(126.8,100.3) B4A9(96.5,100.3)
  rect 11.8x57.1 smd: A5(-49.2,100.3) A6(-9.8,100.3) A7(9.8,100.3) A8(49.2,100.3) B5(68.9,100.3) B6(29.5,100.3) B7(-29.5,100.3) B8(-68.9,100.3)
  Board Outline Layer circle w0.2: c117.3,43.4 r13.8
  Board Outline Layer circle w0.2: c-117.3,43.4 r13.8
  Board Outline Layer circle w10: c117.3,43.4 r13.8
  Board Outline Layer circle w10: c-117.3,43.4 r13.8
  Multi-Layer board cut-out: 117.3,29.6 124.11,31.52 129.07,36.56 130.88,43.4 129.07,50.23 124.11,55.27 117.3,57.2 117.3,57.2 110.5,55.28 105.54,50.24 103.72,43.4 105.53,36.56 110.49,31.52 117.3,29.6
  Multi-Layer board cut-out: -117.3,29.6 -110.49,31.52 -105.53,36.56 -103.72,43.4 -105.53,50.23 -110.49,55.27 -117.3,57.2 -117.3,57.2 -124.1,55.28 -129.06,50.24 -130.88,43.4 -129.07,36.56 -124.11,31.52 -117.3,29.6
  silkscreen extent -170,-200 170,120
USB-C-SMD_TYPEC-304-BCP16#2 [mil]
  oval 39.4x82.7 hole 23.6 slot 70.9 at 90 deg: 13(-170.1,64.3) 14(170.1,64.3)
  oval 39.4x63 hole 23.6 slot 47.2 at 90 deg: 15(-170.1,-100.3) 16(170.1,-100.3)
  rect 23.6x57.1 smd: A1B12(-127,100.3) A4B9(-96.5,100.3) B1A12(126.8,100.3) B4A9(96.5,100.3)
  rect 11.8x57.1 smd: A5(-49.2,100.3) A6(-9.8,100.3) A7(9.8,100.3) A8(49.2,100.3) B5(68.9,100.3) B6(29.5,100.3) B7(-29.5,100.3) B8(-68.9,100.3)
  Board Outline Layer circle w0.2: c117.3,43.4 r13.8
  Board Outline Layer circle w0.2: c-117.3,43.4 r13.8
  Board Outline Layer circle w10: c117.3,43.4 r13.8
  Board Outline Layer circle w10: c-117.3,43.4 r13.8
  Multi-Layer board cut-out: 103.5,43.4 105.41,36.58 110.45,31.61 117.3,29.79 124.14,31.61 129.19,36.58 131.1,43.4 131.1,43.4 129.19,50.22 124.14,55.19 117.3,57.01 110.45,55.19 105.41,50.22 103.5,43.4
  Multi-Layer board cut-out: -131.1,43.4 -129.19,36.58 -124.15,31.61 -117.3,29.79 -110.46,31.61 -105.41,36.58 -103.5,43.4 -103.5,43.4 -105.41,50.22 -110.46,55.19 -117.3,57.01 -124.15,55.19 -129.19,50.22 -131.1,43.4
  silkscreen extent -170,-200 170,120

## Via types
v1: diameter 19.7, hole 11.8, Top Layer to Bottom Layer, 419 vias
v2: diameter 19.68, hole 11.81, Top Layer to Bottom Layer, 364 vias
v3: diameter 31.5, hole 19.68, Top Layer to Bottom Layer, 12 vias
v4: diameter 27.56, hole 19.68, Top Layer to Bottom Layer, 1 vias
